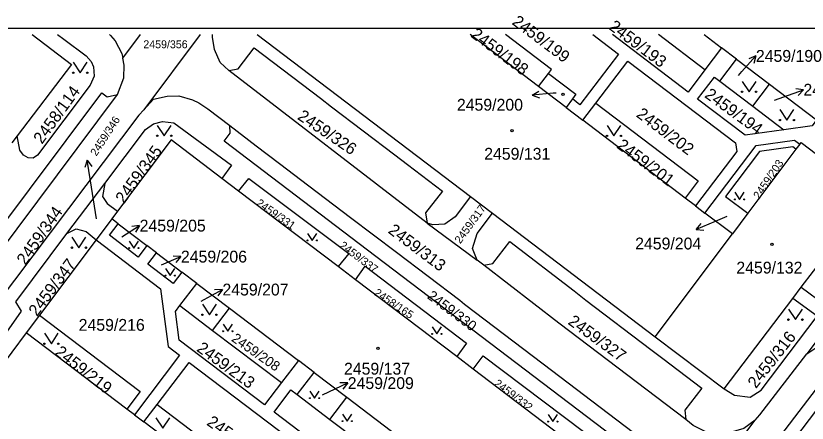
# Model space of a CAD drawing. Extents: x -606208 to -605570, y -1157873 to -1157573.
# Drawn here: x -605870.3 to -605756.7, y -1157633.1 to -1157574.6 of the extents above; entities that cross this region are included whole.
import ezdxf

# ---------------------------------------------------------------- set-up
doc = ezdxf.new("R2010")
doc.units = 0
doc.layers.add('Vrstva 1', color=7, linetype='Continuous')
doc.layers.add('Vrstva 62', color=7, linetype='Continuous')

msp = doc.modelspace()

# ---------------------------------------------------------------- linework, layer by layer
at = {"layer": 'Vrstva 1'}
msp.add_lwpolyline([(-606203.28, -1157873.46), (-605573.29, -1157873.46), (-605573.29, -1157576.47), (-606203.28, -1157576.47)], close=True, dxfattribs=at)
at = {"layer": 'Vrstva 62'}
for p, q in [((-605854.96, -1157580.7), (-605852.41, -1157577.34)), ((-605843.87, -1157577.34), (-605851.95, -1157588.15)), ((-605835.67, -1157577.34), (-605805.07, -1157600.57)), ((-605795.3, -1157584.8), (-605805.1, -1157577.34)), ((-605771.42, -1157582.41), (-605778.09, -1157577.34)), ((-605771.54, -1157577.34), (-605769.02, -1157579.25)), ((-605769.02, -1157579.25), (-605771.42, -1157582.41)), ((-605766.87, -1157580.88), (-605769.02, -1157579.25)), ((-605766.11, -1157582.64), (-605764.1, -1157580.41)), ((-605764.1, -1157580.41), (-605765.14, -1157580.82)), ((-605764.1, -1157580.41), (-605764.4, -1157581.49)), ((-605769.26, -1157584.04), (-605766.87, -1157580.88)), ((-605766.87, -1157580.88), (-605762.17, -1157584.44)), ((-605811.29, -1157604.41), (-605839.74, -1157582.49)), ((-605766.62, -1157583.21), (-605766.11, -1157582.64)), ((-605795.3, -1157584.8), (-605793.85, -1157582.93)), ((-605791.34, -1157587.8), (-605795.3, -1157584.8)), ((-605769.26, -1157584.04), (-605764.57, -1157587.61)), ((-605764.57, -1157587.61), (-605762.17, -1157584.44)), ((-605762.17, -1157584.44), (-605755.39, -1157589.57)), ((-605757.29, -1157585.25), (-605758.4, -1157585.13)), ((-605888.11, -1157629.29), (-605855.73, -1157585.95)), ((-605796.21, -1157586.02), (-605795.26, -1157585.44)), ((-605793.22, -1157585.76), (-605796.21, -1157586.02)), ((-605796.21, -1157586.02), (-605795.17, -1157586.43)), ((-605792.75, -1157585.73), (-605793.22, -1157585.76)), ((-605761.46, -1157586.77), (-605760.11, -1157586.28)), ((-605760.11, -1157586.28), (-605757.29, -1157585.25)), ((-605757.29, -1157585.25), (-605758.06, -1157586.07)), ((-605790.44, -1157586.58), (-605791.34, -1157587.8)), ((-605788.93, -1157589.64), (-605787.07, -1157587.19)), ((-605791.34, -1157587.8), (-605788.93, -1157589.64)), ((-605764.57, -1157587.61), (-605760.1, -1157591)), ((-605774.24, -1157600.81), (-605788.93, -1157589.64)), ((-605870.09, -1157591.86), (-605870.88, -1157592.9)), ((-605757.81, -1157593.07), (-605758.36, -1157593.8)), ((-605758.36, -1157593.8), (-605765.26, -1157602.99)), ((-605860.06, -1157595.36), (-605860.4, -1157596.42)), ((-605859.59, -1157598.32), (-605860.06, -1157595.36)), ((-605860.06, -1157595.36), (-605859.41, -1157596.27)), ((-605862.99, -1157605.9), (-605857.55, -1157598.72)), ((-605858.73, -1157603.8), (-605859.59, -1157598.32)), ((-605838.35, -1157599.8), (-605840.72, -1157598)), ((-605824.06, -1157610.64), (-605838.35, -1157599.8)), ((-605805.07, -1157600.57), (-605801.89, -1157602.99)), ((-605772.77, -1157601.93), (-605774.24, -1157600.81)), ((-605757.6, -1157613.62), (-605747.6, -1157600.44)), ((-605772.77, -1157601.93), (-605771.41, -1157602.96)), ((-605855.69, -1157602.7), (-605856.52, -1157603.8)), ((-605801.89, -1157602.99), (-605778.54, -1157620.72)), ((-605767.48, -1157605.95), (-605771.41, -1157602.96)), ((-605765.26, -1157602.99), (-605767.48, -1157605.95)), ((-605856.52, -1157603.8), (-605858.78, -1157606.81)), ((-605855.61, -1157604.49), (-605856.52, -1157603.8)), ((-605811.29, -1157604.41), (-605804.11, -1157609.71)), ((-605769.94, -1157604.16), (-605772.7, -1157605.33)), ((-605768.29, -1157603.45), (-605769.94, -1157604.16)), ((-605855.61, -1157604.49), (-605851.48, -1157607.62)), ((-605855.07, -1157606.35), (-605852.53, -1157604.76)), ((-605852.53, -1157604.76), (-605853.64, -1157604.87)), ((-605852.53, -1157604.76), (-605853.11, -1157605.72)), ((-605772.7, -1157605.33), (-605771.98, -1157604.48)), ((-605772.7, -1157605.33), (-605771.58, -1157605.4)), ((-605778.54, -1157620.72), (-605767.48, -1157605.95)), ((-605858.78, -1157606.81), (-605866.89, -1157617.61)), ((-605850.13, -1157608.65), (-605851.48, -1157607.62)), ((-605850.13, -1157608.65), (-605846.49, -1157611.42)), ((-605849.38, -1157610.37), (-605846.62, -1157609.2)), ((-605846.62, -1157609.2), (-605847.73, -1157609.13)), ((-605846.62, -1157609.2), (-605847.34, -1157610.05)), ((-605803.15, -1157610.45), (-605804.11, -1157609.71)), ((-605821.58, -1157612.53), (-605824.06, -1157610.64)), ((-605844.34, -1157613.05), (-605846.49, -1157611.42)), ((-605846.75, -1157616.24), (-605844.34, -1157613.05)), ((-605844.34, -1157613.05), (-605839.64, -1157616.62)), ((-605807.03, -1157623.57), (-605821.58, -1157612.53)), ((-605843.28, -1157615.39), (-605840.66, -1157613.94)), ((-605840.66, -1157613.94), (-605841.77, -1157613.98)), ((-605840.66, -1157613.94), (-605841.29, -1157614.86)), ((-605758.82, -1157615.23), (-605757.6, -1157613.62)), ((-605843.69, -1157615.61), (-605843.28, -1157615.39)), ((-605768.68, -1157628.21), (-605758.82, -1157615.23)), ((-605846.75, -1157616.24), (-605842.06, -1157619.8)), ((-605842.06, -1157619.8), (-605839.64, -1157616.62)), ((-605839.64, -1157616.62), (-605829.76, -1157624.12)), ((-605746.58, -1157616.44), (-605760.58, -1157634.9)), ((-605756.81, -1157623.15), (-605746.58, -1157616.44)), ((-605866.89, -1157617.61), (-605868.8, -1157620.15)), ((-605868.8, -1157620.15), (-605875.93, -1157629.65)), ((-605854.36, -1157631.1), (-605868.8, -1157620.15)), ((-605842.06, -1157619.8), (-605832.18, -1157627.3)), ((-605778.54, -1157620.72), (-605768.68, -1157628.21)), ((-605804.68, -1157625.36), (-605807.03, -1157623.57)), ((-605829.76, -1157624.12), (-605832.18, -1157627.3)), ((-605827.51, -1157625.83), (-605829.76, -1157624.12)), ((-605829.93, -1157629.01), (-605827.51, -1157625.83)), ((-605827.51, -1157625.83), (-605822.81, -1157629.39)), ((-605790.3, -1157636.28), (-605804.68, -1157625.36)), ((-605825.4, -1157628.62), (-605822.68, -1157627.35)), ((-605822.68, -1157627.35), (-605823.8, -1157627.32)), ((-605822.68, -1157627.35), (-605823.38, -1157628.23)), ((-605829.93, -1157629.01), (-605825.22, -1157632.57)), ((-605826.31, -1157629.04), (-605825.4, -1157628.62)), ((-605825.22, -1157632.57), (-605822.81, -1157629.39)), ((-605822.81, -1157629.39), (-605812.84, -1157636.96)), ((-605851.94, -1157632.94), (-605850.02, -1157630.42)), ((-605853.29, -1157631.91), (-605854.36, -1157631.1)), ((-605853.29, -1157631.91), (-605851.94, -1157632.94)), ((-605825.22, -1157632.57), (-605815.25, -1157640.15)), ((-605775.19, -1157647.15), (-605764.22, -1157632.67))]:
    msp.add_line(p, q, dxfattribs=at)
for points in [[(-605867.93, -1157577.34), (-605862.31, -1157581.61), (-605870.09, -1157591.86)], [(-605864.3, -1157577.34), (-605863.41, -1157578.01), (-605860.21, -1157580.37), (-605859.49, -1157581.18)], [(-605856.85, -1157577.34), (-605856.72, -1157577.45), (-605856.03, -1157578.22), (-605855.1, -1157580.03), (-605854.96, -1157580.7)], [(-605839.74, -1157582.49), (-605840.99, -1157581.34), (-605841.81, -1157579.47), (-605842.09, -1157577.7), (-605842.06, -1157577.34)], [(-605793.85, -1157582.93), (-605793.42, -1157582.37), (-605800.04, -1157577.34)], [(-605787.51, -1157577.34), (-605783.84, -1157580.13), (-605789.36, -1157587.4), (-605790.44, -1157586.58)], [(-605771.42, -1157582.41), (-605773.83, -1157585.59), (-605784.69, -1157577.34)], [(-605839.74, -1157582.49), (-605838.41, -1157582.24), (-605836.11, -1157579.24), (-605826.58, -1157586.48), (-605825, -1157587.71), (-605815.92, -1157594.62), (-605814.1, -1157595.99), (-605809.09, -1157599.82), (-605811.51, -1157602.93), (-605811.29, -1157604.41)], [(-605862.05, -1157581.32), (-605861.05, -1157582.82), (-605860.05, -1157581.32)], [(-605859.49, -1157581.18), (-605859.17, -1157581.97), (-605859.06, -1157583.3)], [(-605855.73, -1157585.95), (-605854.81, -1157583.56), (-605854.75, -1157581.74), (-605854.96, -1157580.7)], [(-605787.07, -1157587.19), (-605782.49, -1157581.16), (-605767.02, -1157592.9), (-605766.86, -1157594.14), (-605772.77, -1157601.93)], [(-605859.06, -1157583.3), (-605859.64, -1157584.59), (-605867.19, -1157594.64), (-605867.8, -1157595.06), (-605868.53, -1157595.04), (-605869.18, -1157594.66), (-605869.7, -1157593.95), (-605870.09, -1157591.86)], [(-605793.85, -1157582.93), (-605789.95, -1157585.91), (-605790.44, -1157586.58)], [(-605760.1, -1157591), (-605765.67, -1157591.79), (-605772.48, -1157586.62), (-605770.06, -1157583.44), (-605769.26, -1157584.04)], [(-605766.08, -1157584.05), (-605765.08, -1157585.55), (-605764.08, -1157584.05)], [(-605888.11, -1157629.29), (-605888.18, -1157627.77), (-605888.98, -1157627.14), (-605857.95, -1157585.72), (-605857.18, -1157586.29), (-605855.73, -1157585.95)], [(-605851.95, -1157588.15), (-605850.52, -1157586.63), (-605848.56, -1157586.17), (-605846.92, -1157586.15), (-605844.97, -1157586.71), (-605844.03, -1157587.12), (-605842.76, -1157587.98), (-605839.57, -1157590.41)], [(-605787.07, -1157587.19), (-605772.37, -1157598.35), (-605774.24, -1157600.81)], [(-605851.95, -1157588.15), (-605852.65, -1157588.89), (-605880.63, -1157625.97)], [(-605760.66, -1157588.11), (-605759.66, -1157589.61), (-605758.66, -1157588.11)], [(-605755.39, -1157589.57), (-605756.03, -1157590.43), (-605760.1, -1157591)], [(-605731.18, -1157589.31), (-605738.34, -1157598.75), (-605744.53, -1157606.92), (-605756.81, -1157623.15)], [(-605857.55, -1157598.72), (-605851.69, -1157590.98), (-605850.54, -1157590.17), (-605849.24, -1157589.81), (-605847.61, -1157590.02), (-605839.36, -1157596.06), (-605840.72, -1157598)], [(-605850, -1157590.37), (-605849, -1157591.87), (-605848, -1157590.37)], [(-605778.88, -1157636.54), (-605780.04, -1157636.85), (-605780.86, -1157637.89), (-605819.82, -1157608.27), (-605840.4, -1157592.63), (-605839.55, -1157591.51), (-605839.57, -1157590.41)], [(-605839.57, -1157590.41), (-605835.8, -1157593.29), (-605832.45, -1157595.85), (-605828.25, -1157599.04), (-605822.26, -1157603.58), (-605815.67, -1157608.59), (-605806.61, -1157615.48), (-605805.91, -1157616.02), (-605794.65, -1157624.58), (-605782.86, -1157633.54), (-605778.88, -1157636.54)], [(-605785.47, -1157590.39), (-605784.47, -1157591.89), (-605783.47, -1157590.39)], [(-605840.72, -1157598), (-605848.01, -1157592.46), (-605855.69, -1157602.7)], [(-605771.41, -1157602.96), (-605764.07, -1157593.28), (-605758.57, -1157592.5), (-605757.81, -1157593.07)], [(-605728.14, -1157592.1), (-605727.92, -1157593.36), (-605727.16, -1157593.95), (-605730.39, -1157598.18), (-605736.65, -1157606.46), (-605742.95, -1157614.78), (-605749.21, -1157623.05), (-605755.41, -1157631.22), (-605758.56, -1157635.36), (-605759.42, -1157634.71), (-605760.58, -1157634.9)], [(-605757.81, -1157593.07), (-605757.63, -1157592.83), (-605747.6, -1157600.44)], [(-605758.36, -1157593.8), (-605758.82, -1157593.45), (-605763.58, -1157594.12), (-605768.47, -1157600.56), (-605765.26, -1157602.99)], [(-605857.55, -1157598.72), (-605857.85, -1157600.56), (-605857.21, -1157601.6), (-605855.69, -1157602.7)], [(-605838.35, -1157599.8), (-605836.88, -1157598), (-605822.53, -1157608.75), (-605824.06, -1157610.64)], [(-605805.07, -1157600.57), (-605807.27, -1157603.51), (-605808.73, -1157604.57), (-605810.48, -1157604.67), (-605811.29, -1157604.41)], [(-605767.12, -1157599.98), (-605766.45, -1157600.99), (-605765.78, -1157599.98)], [(-605757.6, -1157613.62), (-605754.12, -1157616.18), (-605745.42, -1157604.68), (-605745.15, -1157602.58), (-605746.08, -1157601.43), (-605747.11, -1157600.65), (-605747.6, -1157600.44)], [(-605804.11, -1157609.71), (-605804.78, -1157608.06), (-605804.12, -1157605.91), (-605801.89, -1157602.99)], [(-605862.99, -1157605.9), (-605861.65, -1157605.22), (-605860.2, -1157605.6), (-605858.78, -1157606.81)], [(-605851.48, -1157607.62), (-605852.74, -1157609.27), (-605856.86, -1157606.14), (-605855.61, -1157604.49)], [(-605875.93, -1157629.65), (-605871.9, -1157620.54), (-605869.49, -1157617.02), (-605870.32, -1157615.7), (-605862.99, -1157605.9)], [(-605862.25, -1157606.43), (-605861.25, -1157607.93), (-605860.25, -1157606.43)], [(-605828.43, -1157605.87), (-605827.76, -1157606.88), (-605827.09, -1157605.87)], [(-605858.78, -1157606.81), (-605849.54, -1157613.83), (-605848.44, -1157622.11), (-605846.8, -1157623.36), (-605853.29, -1157631.91)], [(-605854.04, -1157606.98), (-605853.37, -1157607.99), (-605852.7, -1157606.98)], [(-605803.15, -1157610.45), (-605801.83, -1157610.22), (-605799.43, -1157607.06), (-605790.19, -1157614.13), (-605788.52, -1157615.44), (-605779.17, -1157622.53), (-605777.45, -1157623.84), (-605771.87, -1157628.09), (-605774.29, -1157631.26), (-605774.17, -1157632.61)], [(-605846.49, -1157611.42), (-605847.74, -1157613.07), (-605851.38, -1157610.3), (-605850.13, -1157608.65)], [(-605848.8, -1157610.92), (-605848.13, -1157611.93), (-605847.46, -1157610.92)], [(-605821.58, -1157612.53), (-605820.18, -1157610.59), (-605805.61, -1157621.63), (-605807.03, -1157623.57)], [(-605774.17, -1157632.61), (-605792.36, -1157618.77), (-605803.15, -1157610.45)], [(-605768.68, -1157628.21), (-605767.19, -1157629.12), (-605764.95, -1157629.39), (-605763.34, -1157628.36), (-605755.33, -1157617.77), (-605758.82, -1157615.23)], [(-605832.18, -1157627.3), (-605834.6, -1157630.49), (-605846.85, -1157621.19), (-605847.4, -1157617.08), (-605846.75, -1157616.24)], [(-605843.52, -1157616.05), (-605842.52, -1157617.55), (-605841.52, -1157616.05)], [(-605759.44, -1157616.76), (-605758.44, -1157618.26), (-605757.44, -1157616.76)], [(-605866.89, -1157617.61), (-605852.45, -1157628.58), (-605854.36, -1157631.1)], [(-605840.57, -1157618.92), (-605839.9, -1157619.93), (-605839.23, -1157618.92)], [(-605866.2, -1157620.22), (-605865.2, -1157621.72), (-605864.2, -1157620.22)], [(-605810.58, -1157619.3), (-605809.91, -1157620.31), (-605809.24, -1157619.3)], [(-605804.68, -1157625.36), (-605803.23, -1157623.47), (-605788.86, -1157634.32), (-605790.3, -1157636.28)], [(-605764.22, -1157632.67), (-605763.52, -1157631.92), (-605756.81, -1157623.15)], [(-605850.02, -1157630.42), (-605845.44, -1157624.39), (-605827.68, -1157637.87), (-605833.2, -1157645.14), (-605834.19, -1157644.39)], [(-605815.25, -1157640.15), (-605817.67, -1157643.34), (-605833.24, -1157631.52), (-605830.83, -1157628.33), (-605829.93, -1157629.01)], [(-605828.09, -1157628.52), (-605827.42, -1157629.53), (-605826.75, -1157628.52)], [(-605850.02, -1157630.42), (-605837.04, -1157640.28), (-605837.43, -1157640.8)], [(-605850.19, -1157632.36), (-605849.19, -1157633.86), (-605848.19, -1157632.36)], [(-605823.41, -1157631.82), (-605822.74, -1157632.83), (-605822.07, -1157631.82)], [(-605793.92, -1157631.88), (-605793.25, -1157632.89), (-605792.58, -1157631.88)], [(-605764.22, -1157632.67), (-605765.86, -1157633.89), (-605768.49, -1157634.64), (-605771.31, -1157634.35), (-605773.09, -1157633.43), (-605774.17, -1157632.61)], [(-605837.43, -1157640.8), (-605838.95, -1157642.79), (-605851.94, -1157632.94)]]:
    msp.add_lwpolyline(points, dxfattribs=at)
for centre, radius in [((-605862.05, -1157582.82), 0.1), ((-605860.05, -1157582.82), 0.1), ((-605791.77, -1157585.9), 0.175), ((-605766.08, -1157585.55), 0.1), ((-605764.08, -1157585.55), 0.1), ((-605760.66, -1157589.61), 0.1), ((-605758.66, -1157589.61), 0.1), ((-605850, -1157591.87), 0.1), ((-605848, -1157591.87), 0.1), ((-605799.09, -1157591.12), 0.175), ((-605785.47, -1157591.89), 0.1), ((-605783.47, -1157591.89), 0.1), ((-605767.12, -1157600.99), 0.067), ((-605765.78, -1157600.99), 0.067), ((-605862.25, -1157607.93), 0.1), ((-605860.25, -1157607.93), 0.1), ((-605828.43, -1157606.88), 0.067), ((-605827.09, -1157606.88), 0.067), ((-605761.8, -1157607.44), 0.175), ((-605854.04, -1157607.99), 0.067), ((-605852.7, -1157607.99), 0.067), ((-605848.8, -1157611.93), 0.067), ((-605847.46, -1157611.93), 0.067), ((-605843.52, -1157617.55), 0.1), ((-605841.52, -1157617.55), 0.1), ((-605759.44, -1157618.26), 0.1), ((-605757.44, -1157618.26), 0.1), ((-605840.57, -1157619.93), 0.067), ((-605839.23, -1157619.93), 0.067), ((-605810.58, -1157620.31), 0.067), ((-605809.24, -1157620.31), 0.067), ((-605866.2, -1157621.72), 0.1), ((-605864.2, -1157621.72), 0.1), ((-605818.34, -1157622.39), 0.175), ((-605828.09, -1157629.53), 0.067), ((-605826.75, -1157629.53), 0.067), ((-605823.41, -1157632.83), 0.067), ((-605822.07, -1157632.83), 0.067), ((-605793.92, -1157632.89), 0.067), ((-605792.58, -1157632.89), 0.067)]:
    msp.add_circle(centre, radius, dxfattribs=at)

# ---------------------------------------------------------------- texts
for s, height, rotation, p in [('2459/199', 1.7, 323, (-605799.21, -1157575.77)), ('2459/193', 1.7, 323, (-605785.33, -1157576.46)), ('2459/198', 1.7, 323, (-605805.13, -1157577.59)), ('2458/114', 1.7, 54, (-605866.55, -1157593.16)), ('2459/194', 1.7, 324, (-605771.59, -1157586.25)), ('2459/326', 1.7, 326, (-605830, -1157589.4)), ('2459/202', 1.7, 323, (-605781.39, -1157589.04)), ('2459/346', 1.139, 57, (-605858.74, -1157594.87)), ('2459/201', 1.7, 323, (-605784.19, -1157593.51)), ('2459/345', 1.7, 54, (-605854.78, -1157601.73)), ('2459/203', 1.139, 56, (-605763.63, -1157601.04)), ('2459/331', 1.139, 325, (-605835.9, -1157601.76)), ('2459/344', 1.7, 55, (-605868.92, -1157610.54)), ('2459/317', 1.139, 54, (-605806.52, -1157607.44)), ('2459/313', 1.7, 323, (-605817, -1157605.71)), ('2459/337', 1.139, 323, (-605823.95, -1157607.82)), ('2459/347', 1.7, 53, (-605867.27, -1157617.9)), ('2458/165', 1.139, 326, (-605818.99, -1157614.65)), ('2459/330', 1.456, 323, (-605811.37, -1157615.11)), ('2459/327', 1.7, 324, (-605791.19, -1157618.81)), ('2459/208', 1.41, 325, (-605839.46, -1157621.24)), ('2459/316', 1.7, 52, (-605764.1, -1157628.24)), ('2459/219', 1.7, 322, (-605864.82, -1157623.18)), ('2459/213', 1.7, 324, (-605844.47, -1157622.67)), ('2459/332', 1.139, 323, (-605801.76, -1157627.63)), ('2459/217', 1.7, 325, (-605843.03, -1157633.29))]:
    msp.add_text(s, height=height, rotation=rotation, dxfattribs=at).set_placement(p)
for s, height, p in [('2459/356', 1.139, (-605852, -1157579.3)), ('2459/190', 1.7, (-605764.11, -1157581.25)), ('2459/191', 1.7, (-605757.29, -1157586.11)), ('2459/200', 1.7, (-605807.01, -1157588.26)), ('2459/131', 1.7, (-605803.09, -1157595.3)), ('2459/205', 1.7, (-605852.53, -1157605.61)), ('2459/204', 1.7, (-605781.43, -1157608.18)), ('2459/206', 1.7, (-605846.61, -1157610.06)), ('2459/132', 1.7, (-605766.91, -1157611.64)), ('2459/207', 1.7, (-605840.65, -1157614.79)), ('2459/216', 1.7, (-605861.28, -1157619.86)), ('2459/137', 1.7, (-605823.21, -1157626.15)), ('2459/209', 1.7, (-605822.67, -1157628.22))]:
    msp.add_text(s, height=height, dxfattribs=at).set_placement(p)

doc.saveas('drawing.dxf')
